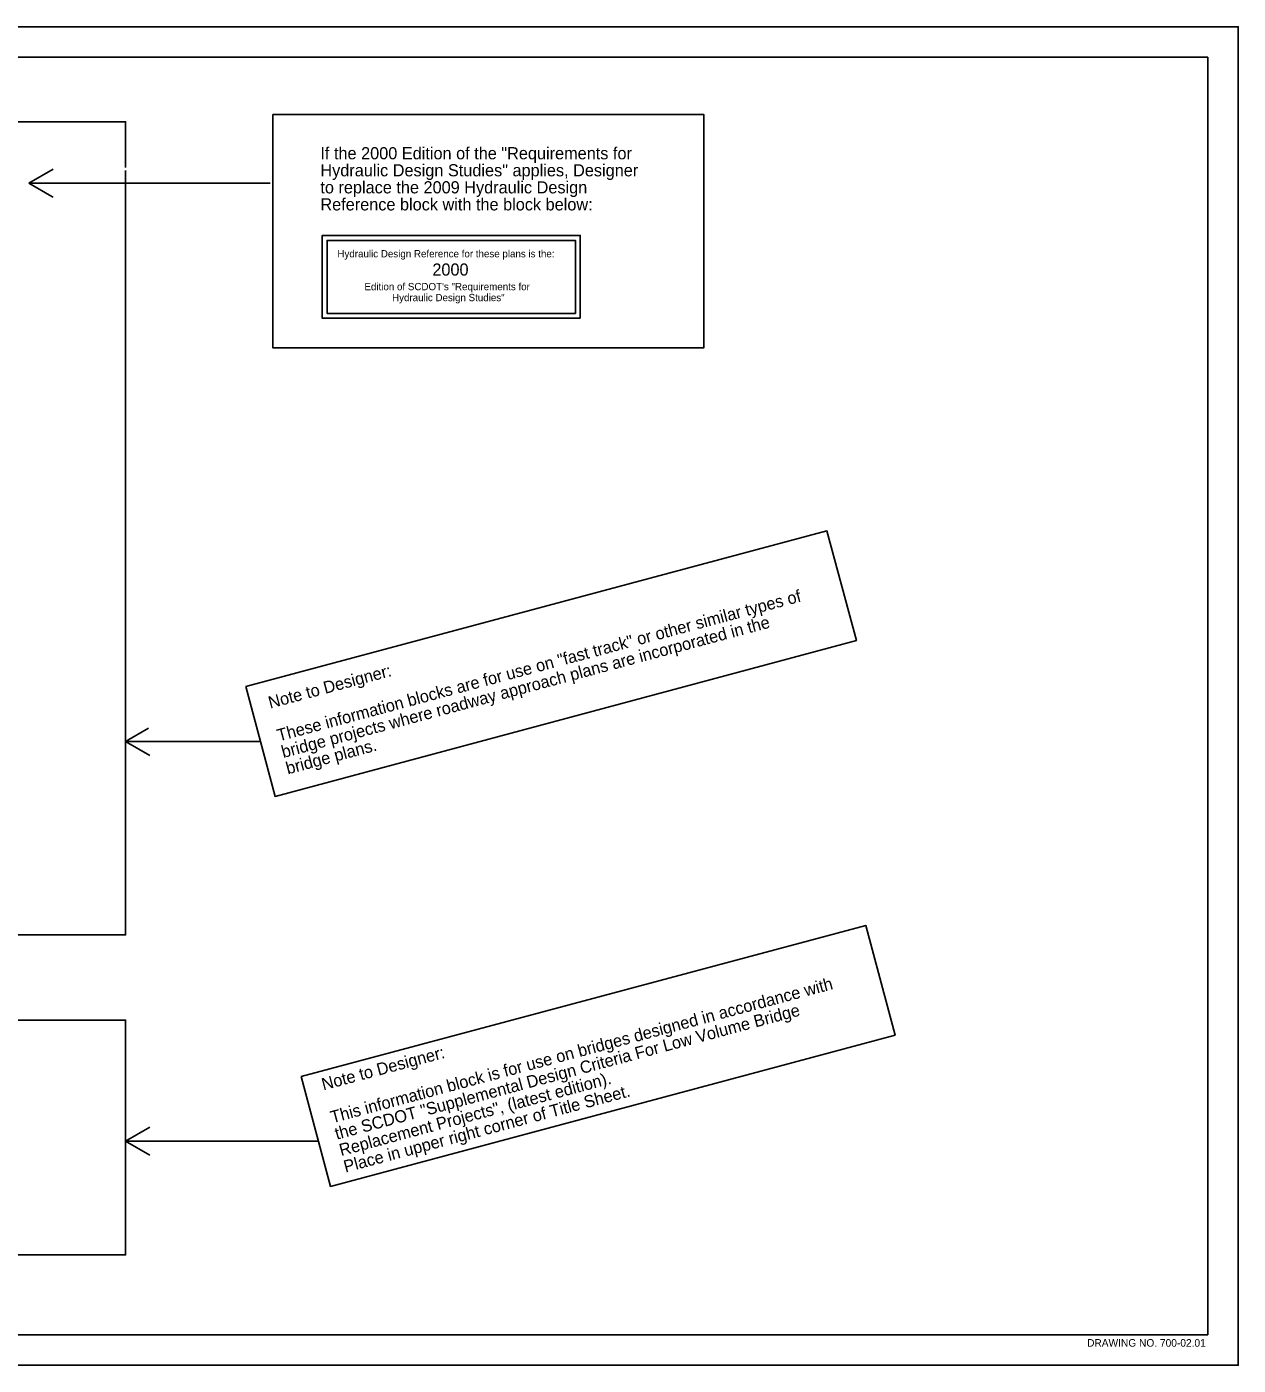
# Model space of a CAD drawing. Extents: x 0 to 3450, y -1150 to 1100.
# Drawn here: x 2455 to 3450, y 0 to 1100 of the extents above; entities that cross this region are included whole.
import ezdxf

# ---------------------------------------------------------------- set-up
doc = ezdxf.new("R2010")
doc.units = 0
for name, color, linetype in [('BR_AUTO DIMENSION', 7, 'Continuous'), ('BR_BORDER LINES', 7, 'Continuous'), ('BR_DETAILS', 7, 'Continuous'), ('BR_TABLE LINES', 7, 'Continuous'), ('BR_TEXT', 7, 'Continuous'), ('RD_SHT_IplotShp', 7, 'Continuous')]:
    doc.layers.add(name, color=color, linetype=linetype)

msp = doc.modelspace()

# ---------------------------------------------------------------- linework, layer by layer
at = {"layer": 'BR_BORDER LINES'}
for p, q in [((1750, 1100.1), (3450, 1100.1)), ((3425, 1075.1), (1850, 1075.1)), ((3425, 25.1), (3425, 1075.1)), ((1850, 25.1), (3425, 25.1)), ((1750, 0.1), (3450, 0.1))]:
    msp.add_line(p, q, dxfattribs=at)
at = {"layer": 'BR_DETAILS'}
for points in [[(2909.3, 860.6), (2697.3, 860.6), (2697.3, 928.6), (2909.3, 928.6)], [(2905.3, 864.6), (2701.3, 864.6), (2701.3, 924.6), (2905.3, 924.6)]]:
    msp.add_lwpolyline(points, close=True, dxfattribs=at)
at = {"layer": 'BR_TABLE LINES'}
for p, q in [((2456.2, 971.6), (2476.2, 983.2)), ((2456.2, 971.6), (2654.5, 971.6)), ((2456.2, 971.6), (2475, 960.7)), ((2475.1, 960.7), (2476.2, 960.1)), ((2535.7, 512.7), (2554.5, 523.6)), ((2535.7, 512.7), (2646.5, 512.7)), ((2535.7, 512.7), (2555.7, 501.2)), ((2535.7, 184.1), (2555.7, 195.7)), ((2535.7, 184.1), (2555.7, 172.6)), ((2535.7, 184.1), (2693.3, 184.1))]:
    msp.add_line(p, q, dxfattribs=at)
for points in [[(2656.7, 1027.9), (3011, 1027.9), (3011, 836.3), (2656.7, 836.3)], [(2634.4, 557.8), (3112, 685.8), (3136.2, 595.6), (2658.6, 467.6)], [(2680.1, 237.3), (3143.9, 361.6), (3168, 271.4), (2704.2, 147.1)], [(1898.1, 283.8), (2535.7, 283.8), (2535.7, 90.7), (1898.1, 90.7)]]:
    msp.add_lwpolyline(points, close=True, dxfattribs=at)
for points in [[(2535.7, 984.4), (2535.7, 1022.1), (1898.1, 1022.1), (1898.1, 353.8), (2535.7, 353.8), (2535.7, 982)], [(2475, 982.5), (2475, 982.5)]]:
    msp.add_lwpolyline(points, dxfattribs=at)
at = {"layer": 'RD_SHT_IplotShp'}
msp.add_lwpolyline([(1750, 1100.1), (3450, 1100.1), (3450, 0.1), (1750, 0.1)], close=True, dxfattribs=at)

# ---------------------------------------------------------------- texts
at = {"layer": 'BR_AUTO DIMENSION'}
msp.add_text('DRAWING NO. 700-02.01', height=6.25, dxfattribs=at).set_placement((3325.8, 15.3))
at = {"layer": 'BR_DETAILS'}
for s, height, p in [('Hydraulic Design Reference for these plans is the:', 6, (2709.8, 910.6)), ('2000', 10, (2787.8, 895.6)), ('Edition of SCDOT\'s "Requirements for', 6, (2732, 883.6)), ('Hydraulic Design Studies"', 6, (2754.7, 874.6))]:
    msp.add_text(s, height=height, dxfattribs=at).set_placement(p)
at = {"layer": 'BR_TEXT'}
for s, rotation, p in [('If the 2000 Edition of the "Requirements for', 360, (2695.8, 991.2)), ('Hydraulic Design Studies" applies, Designer ', 360, (2695.8, 977.2)), ('to replace the 2009 Hydraulic Design ', 360, (2695.8, 963.2)), ('Reference block with the block below:', 360, (2695.8, 949.2)), ('These information blocks are for use on "fast track" or other similar types of ', 15, (2661.7, 512.7)), ('bridge projects where roadway approach plans are incorporated in the', 15, (2665.3, 499.1)), ('Note to Designer:', 15, (2654.5, 539.7)), ('bridge plans.', 15, (2669, 485.6)), ('This information block is for use on bridges designed in accordance with', 15, (2705.6, 198.9)), ('the SCDOT "Supplemental Design Criteria For Low Volume Bridge', 15, (2709.2, 185.4)), ('Note to Designer:', 15, (2698.3, 225.9)), ('Replacement Projects", (latest edition).', 15, (2712.8, 171.9)), ('Place in upper right corner of Title Sheet.', 15, (2716.4, 158.3))]:
    msp.add_text(s, height=10, rotation=rotation, dxfattribs=at).set_placement(p)

doc.saveas('drawing.dxf')
